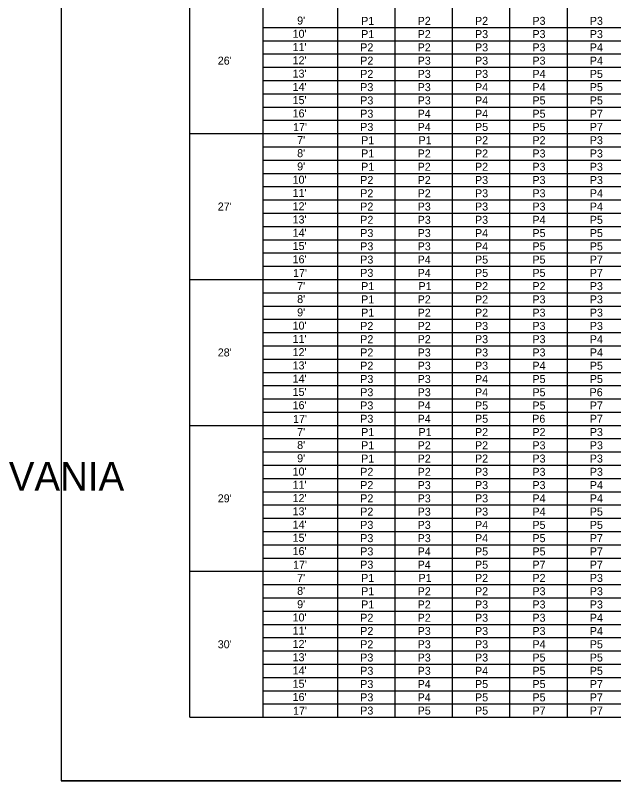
# Model space of a CAD drawing. Extents: x 637580 to 641008, y 294594 to 295782.
# Drawn here: x 640126.1 to 640350.4, y 295202.6 to 295489.6 of the extents above; entities that cross this region are included whole.
import ezdxf

# ---------------------------------------------------------------- set-up
doc = ezdxf.new("R2010")
doc.units = 0
doc.layers.add('1', color=7, linetype='Continuous')
doc.layers.add('2', color=7, linetype='Continuous')

msp = doc.modelspace()

# ---------------------------------------------------------------- linework, layer by layer
at = {"layer": '1'}
for p, q in [((640143.31, 295766.63), (640143.31, 295202.63)), ((640191.43, 295226.43), (640191.43, 295743.08)), ((640218.95, 295226.43), (640218.95, 295735.41)), ((640191.43, 295445.22), (640526.66, 295445.22)), ((640191.43, 295390.52), (640526.66, 295390.52)), ((640191.43, 295335.82), (640526.66, 295335.82)), ((640191.43, 295281.12), (640526.66, 295281.12)), ((640191.43, 295226.43), (640526.66, 295226.43)), ((640929.31, 295202.63), (640143.31, 295202.63)), ((640143.31, 295202.63), (640729.31, 295202.63))]:
    msp.add_line(p, q, dxfattribs=at)
at = {"layer": '2'}
for p, q in [((640246.95, 295226.43), (640246.95, 295735.41)), ((640268.47, 295226.43), (640268.47, 295728.06)), ((640289.99, 295226.43), (640289.99, 295728.06)), ((640311.5, 295226.43), (640311.5, 295728.06)), ((640333.02, 295226.43), (640333.02, 295728.06)), ((640218.95, 295485), (640526.66, 295485)), ((640218.95, 295480.02), (640526.66, 295480.02)), ((640218.95, 295475.05), (640526.66, 295475.05)), ((640218.95, 295470.08), (640526.66, 295470.08)), ((640218.95, 295465.11), (640526.66, 295465.11)), ((640218.95, 295460.13), (640526.66, 295460.13)), ((640218.95, 295455.16), (640526.66, 295455.16)), ((640218.95, 295450.19), (640526.66, 295450.19)), ((640218.95, 295440.24), (640526.66, 295440.24)), ((640218.95, 295435.27), (640526.66, 295435.27)), ((640218.95, 295430.3), (640526.66, 295430.3)), ((640218.95, 295425.33), (640526.66, 295425.33)), ((640218.95, 295420.35), (640526.66, 295420.35)), ((640218.95, 295415.38), (640526.66, 295415.38)), ((640218.95, 295410.41), (640526.66, 295410.41)), ((640218.95, 295405.44), (640526.66, 295405.44)), ((640218.95, 295400.46), (640526.66, 295400.46)), ((640218.95, 295395.49), (640526.66, 295395.49)), ((640218.95, 295385.55), (640526.66, 295385.55)), ((640218.95, 295380.57), (640526.66, 295380.57)), ((640218.95, 295375.6), (640526.66, 295375.6)), ((640218.95, 295370.63), (640526.66, 295370.63)), ((640218.95, 295365.66), (640526.66, 295365.66)), ((640218.95, 295360.68), (640526.66, 295360.68)), ((640218.95, 295355.71), (640526.66, 295355.71)), ((640218.95, 295350.74), (640526.66, 295350.74)), ((640218.95, 295345.77), (640526.66, 295345.77)), ((640218.95, 295340.79), (640526.66, 295340.79)), ((640218.95, 295330.85), (640526.66, 295330.85)), ((640218.95, 295325.88), (640526.66, 295325.88)), ((640218.95, 295320.9), (640526.66, 295320.9)), ((640218.95, 295315.93), (640526.66, 295315.93)), ((640218.95, 295310.96), (640526.66, 295310.96)), ((640218.95, 295305.99), (640526.66, 295305.99)), ((640218.95, 295301.01), (640526.66, 295301.01)), ((640218.95, 295296.04), (640526.66, 295296.04)), ((640218.95, 295291.07), (640526.66, 295291.07)), ((640218.95, 295286.1), (640526.66, 295286.1)), ((640218.95, 295276.15), (640526.66, 295276.15)), ((640218.95, 295271.18), (640526.66, 295271.18)), ((640218.95, 295266.21), (640526.66, 295266.21)), ((640218.95, 295261.23), (640526.66, 295261.23)), ((640218.95, 295256.26), (640526.66, 295256.26)), ((640218.95, 295251.29), (640526.66, 295251.29)), ((640218.95, 295246.32), (640526.66, 295246.32)), ((640218.95, 295241.34), (640526.66, 295241.34)), ((640218.95, 295236.37), (640526.66, 295236.37)), ((640218.95, 295231.4), (640526.66, 295231.4))]:
    msp.add_line(p, q, dxfattribs=at)

# ---------------------------------------------------------------- texts
at = {"layer": '1'}
for s, height, p in [("9'", 3, (640231.71, 295486.09)), ('P1', 3, (640255.7, 295485.98)), ('P2', 3, (640276.88, 295485.98)), ('P2', 3, (640298.39, 295485.98)), ('P3', 3, (640319.91, 295485.98)), ('P3', 3, (640341.42, 295485.98)), ("10'", 3, (640230.01, 295481.12)), ('P1', 3, (640255.7, 295481.01)), ('P2', 3, (640276.88, 295481.01)), ('P3', 3, (640298.39, 295481.01)), ('P3', 3, (640319.91, 295481.01)), ('P3', 3, (640341.42, 295481.01)), ("11'", 3, (640230.01, 295476.15)), ('P2', 3, (640255.36, 295476.04)), ('P2', 3, (640276.88, 295476.04)), ('P3', 3, (640298.39, 295476.04)), ('P3', 3, (640319.91, 295476.04)), ('P4', 3, (640341.42, 295476.04)), ("26'", 3, (640201.95, 295471.06)), ("12'", 3, (640230.01, 295471.18)), ('P2', 3, (640255.36, 295471.06)), ('P3', 3, (640276.88, 295471.06)), ('P3', 3, (640298.39, 295471.06)), ('P3', 3, (640319.91, 295471.06)), ('P4', 3, (640341.42, 295471.06)), ("13'", 3, (640230.01, 295466.2)), ('P2', 3, (640255.36, 295466.09)), ('P3', 3, (640276.88, 295466.09)), ('P3', 3, (640298.39, 295466.09)), ('P4', 3, (640319.91, 295466.09)), ('P5', 3, (640341.42, 295466.09)), ("14'", 3, (640230.01, 295461.23)), ('P3', 3, (640255.36, 295461.12)), ('P3', 3, (640276.88, 295461.12)), ('P4', 3, (640298.39, 295461.12)), ('P4', 3, (640319.91, 295461.12)), ('P5', 3, (640341.42, 295461.12)), ("15'", 3, (640230.01, 295456.26)), ('P3', 3, (640255.36, 295456.15)), ('P3', 3, (640276.88, 295456.15)), ('P4', 3, (640298.39, 295456.15)), ('P5', 3, (640319.91, 295456.15)), ('P5', 3, (640341.42, 295456.15)), ("16'", 3, (640230.01, 295451.29)), ('P3', 3, (640255.36, 295451.17)), ('P4', 3, (640276.88, 295451.17)), ('P4', 3, (640298.39, 295451.17)), ('P5', 3, (640319.91, 295451.17)), ('P7', 3, (640341.42, 295451.17)), ("17'", 3, (640230.17, 295446.14)), ('P3', 3, (640255.36, 295446.2)), ('P4', 3, (640276.88, 295446.2)), ('P5', 3, (640298.39, 295446.2)), ('P5', 3, (640319.91, 295446.2)), ('P7', 3, (640341.42, 295446.2)), ("7'", 3, (640231.71, 295441.25)), ('P1', 3, (640255.7, 295441.23)), ('P1', 3, (640277.22, 295441.23)), ('P2', 3, (640298.39, 295441.23)), ('P2', 3, (640319.91, 295441.23)), ('P3', 3, (640341.42, 295441.23)), ("8'", 3, (640231.71, 295436.37)), ('P1', 3, (640255.7, 295436.26)), ('P2', 3, (640276.88, 295436.26)), ('P2', 3, (640298.39, 295436.26)), ('P3', 3, (640319.91, 295436.26)), ('P3', 3, (640341.42, 295436.26)), ("9'", 3, (640231.71, 295431.4)), ('P1', 3, (640255.7, 295431.28)), ('P2', 3, (640276.88, 295431.28)), ('P2', 3, (640298.39, 295431.28)), ('P3', 3, (640319.91, 295431.28)), ('P3', 3, (640341.42, 295431.28)), ("10'", 3, (640230.01, 295426.42)), ('P2', 3, (640255.36, 295426.31)), ('P2', 3, (640276.88, 295426.31)), ('P3', 3, (640298.39, 295426.31)), ('P3', 3, (640319.91, 295426.31)), ('P3', 3, (640341.42, 295426.31)), ("11'", 3, (640230.01, 295421.45)), ('P2', 3, (640255.36, 295421.34)), ('P2', 3, (640276.88, 295421.34)), ('P3', 3, (640298.39, 295421.34)), ('P3', 3, (640319.91, 295421.34)), ('P4', 3, (640341.42, 295421.34)), ("27'", 3, (640201.95, 295416.37)), ("12'", 3, (640230.01, 295416.48)), ('P2', 3, (640255.36, 295416.37)), ('P3', 3, (640276.88, 295416.37)), ('P3', 3, (640298.39, 295416.37)), ('P3', 3, (640319.91, 295416.37)), ('P4', 3, (640341.42, 295416.37)), ("13'", 3, (640230.01, 295411.51)), ('P2', 3, (640255.36, 295411.39)), ('P3', 3, (640276.88, 295411.39)), ('P3', 3, (640298.39, 295411.39)), ('P4', 3, (640319.91, 295411.39)), ('P5', 3, (640341.42, 295411.39)), ("14'", 3, (640230.01, 295406.53)), ('P3', 3, (640255.36, 295406.42)), ('P3', 3, (640276.88, 295406.42)), ('P4', 3, (640298.39, 295406.42)), ('P5', 3, (640319.91, 295406.42)), ('P5', 3, (640341.42, 295406.42)), ("15'", 3, (640230.01, 295401.56)), ('P3', 3, (640255.36, 295401.45)), ('P3', 3, (640276.88, 295401.45)), ('P4', 3, (640298.39, 295401.45)), ('P5', 3, (640319.91, 295401.45)), ('P5', 3, (640341.42, 295401.45)), ("16'", 3, (640230.01, 295396.59)), ('P3', 3, (640255.36, 295396.48)), ('P4', 3, (640276.88, 295396.48)), ('P5', 3, (640298.39, 295396.48)), ('P5', 3, (640319.91, 295396.48)), ('P7', 3, (640341.42, 295396.48)), ('P3', 3, (640255.36, 295391.5)), ("17'", 3, (640230.17, 295391.44)), ('P4', 3, (640276.88, 295391.5)), ('P5', 3, (640298.39, 295391.5)), ('P5', 3, (640319.91, 295391.5)), ('P7', 3, (640341.42, 295391.5)), ("7'", 3, (640231.71, 295386.55)), ('P1', 3, (640255.7, 295386.53)), ('P1', 3, (640277.22, 295386.53)), ('P2', 3, (640298.39, 295386.53)), ('P2', 3, (640319.91, 295386.53)), ('P3', 3, (640341.42, 295386.53)), ("8'", 3, (640231.71, 295381.67)), ('P1', 3, (640255.7, 295381.56)), ('P2', 3, (640276.88, 295381.56)), ('P2', 3, (640298.39, 295381.56)), ('P3', 3, (640319.91, 295381.56)), ('P3', 3, (640341.42, 295381.56)), ("9'", 3, (640231.71, 295376.7)), ('P1', 3, (640255.7, 295376.59)), ('P2', 3, (640276.88, 295376.59)), ('P2', 3, (640298.39, 295376.59)), ('P3', 3, (640319.91, 295376.59)), ('P3', 3, (640341.42, 295376.59)), ("10'", 3, (640230.01, 295371.73)), ('P2', 3, (640255.36, 295371.61)), ('P2', 3, (640276.88, 295371.61)), ('P3', 3, (640298.39, 295371.61)), ('P3', 3, (640319.91, 295371.61)), ('P3', 3, (640341.42, 295371.61)), ("11'", 3, (640230.01, 295366.75)), ('P2', 3, (640255.36, 295366.64)), ('P2', 3, (640276.88, 295366.64)), ('P3', 3, (640298.39, 295366.64)), ('P3', 3, (640319.91, 295366.64)), ('P4', 3, (640341.42, 295366.64)), ("28'", 3, (640201.95, 295361.67)), ("12'", 3, (640230.01, 295361.78)), ('P2', 3, (640255.36, 295361.67)), ('P3', 3, (640276.88, 295361.67)), ('P3', 3, (640298.39, 295361.67)), ('P3', 3, (640319.91, 295361.67)), ('P4', 3, (640341.42, 295361.67)), ("13'", 3, (640230.01, 295356.81)), ('P2', 3, (640255.36, 295356.7)), ('P3', 3, (640276.88, 295356.7)), ('P3', 3, (640298.39, 295356.7)), ('P4', 3, (640319.91, 295356.7)), ('P5', 3, (640341.42, 295356.7)), ("14'", 3, (640230.01, 295351.84)), ('P3', 3, (640255.36, 295351.72)), ('P3', 3, (640276.88, 295351.72)), ('P4', 3, (640298.39, 295351.72)), ('P5', 3, (640319.91, 295351.72)), ('P5', 3, (640341.42, 295351.72)), ("15'", 3, (640230.01, 295346.86)), ('P3', 3, (640255.36, 295346.75)), ('P3', 3, (640276.88, 295346.75)), ('P4', 3, (640298.39, 295346.75)), ('P5', 3, (640319.91, 295346.75)), ('P6', 3, (640341.34, 295346.75)), ("16'", 3, (640230.01, 295341.89)), ('P3', 3, (640255.36, 295341.78)), ('P4', 3, (640276.88, 295341.78)), ('P5', 3, (640298.39, 295341.78)), ('P5', 3, (640319.91, 295341.78)), ('P7', 3, (640341.42, 295341.78)), ("17'", 3, (640230.17, 295336.74)), ('P3', 3, (640255.36, 295336.81)), ('P4', 3, (640276.88, 295336.81)), ('P5', 3, (640298.39, 295336.81)), ('P6', 3, (640319.83, 295336.81)), ('P7', 3, (640341.42, 295336.81)), ("7'", 3, (640231.71, 295331.85)), ('P1', 3, (640255.7, 295331.83)), ('P1', 3, (640277.22, 295331.83)), ('P2', 3, (640298.39, 295331.83)), ('P2', 3, (640319.91, 295331.83)), ('P3', 3, (640341.42, 295331.83)), ("8'", 3, (640231.71, 295326.97)), ('P1', 3, (640255.7, 295326.86)), ('P2', 3, (640276.88, 295326.86)), ('P2', 3, (640298.39, 295326.86)), ('P3', 3, (640319.91, 295326.86)), ('P3', 3, (640341.42, 295326.86)), ("9'", 3, (640231.71, 295322)), ('P1', 3, (640255.7, 295321.89)), ('P2', 3, (640276.88, 295321.89)), ('P2', 3, (640298.39, 295321.89)), ('P3', 3, (640319.91, 295321.89)), ('P3', 3, (640341.42, 295321.89)), ('COMMONWEALTH OF PENNSYLVANIA', 10.7828, (639900.9, 295311.36)), ("10'", 3, (640230.01, 295317.03)), ('P2', 3, (640255.36, 295316.92)), ('P2', 3, (640276.88, 295316.92)), ('P3', 3, (640298.39, 295316.92)), ('P3', 3, (640319.91, 295316.92)), ('P3', 3, (640341.42, 295316.92)), ("11'", 3, (640230.01, 295312.06)), ('P2', 3, (640255.36, 295311.94)), ('P3', 3, (640276.88, 295311.94)), ('P3', 3, (640298.39, 295311.94)), ('P3', 3, (640319.91, 295311.94)), ('P4', 3, (640341.42, 295311.94)), ("29'", 3, (640201.95, 295306.97)), ("12'", 3, (640230.01, 295307.08)), ('P2', 3, (640255.36, 295306.97)), ('P3', 3, (640276.88, 295306.97)), ('P3', 3, (640298.39, 295306.97)), ('P4', 3, (640319.91, 295306.97)), ('P4', 3, (640341.42, 295306.97)), ("13'", 3, (640230.01, 295302.11)), ('P2', 3, (640255.36, 295302)), ('P3', 3, (640276.88, 295302)), ('P3', 3, (640298.39, 295302)), ('P4', 3, (640319.91, 295302)), ('P5', 3, (640341.42, 295302)), ("14'", 3, (640230.01, 295297.14)), ('P3', 3, (640255.36, 295297.03)), ('P3', 3, (640276.88, 295297.03)), ('P4', 3, (640298.39, 295297.03)), ('P5', 3, (640319.91, 295297.03)), ('P5', 3, (640341.42, 295297.03)), ("15'", 3, (640230.01, 295292.17)), ('P3', 3, (640255.36, 295292.05)), ('P3', 3, (640276.88, 295292.05)), ('P4', 3, (640298.39, 295292.05)), ('P5', 3, (640319.91, 295292.05)), ('P7', 3, (640341.42, 295292.05)), ("16'", 3, (640230.01, 295287.19)), ('P3', 3, (640255.36, 295287.08)), ('P4', 3, (640276.88, 295287.08)), ('P5', 3, (640298.39, 295287.08)), ('P5', 3, (640319.91, 295287.08)), ('P7', 3, (640341.42, 295287.08)), ("17'", 3, (640230.17, 295282.05)), ('P3', 3, (640255.36, 295282.11)), ('P4', 3, (640276.88, 295282.11)), ('P5', 3, (640298.39, 295282.11)), ('P7', 3, (640319.91, 295282.11)), ('P7', 3, (640341.42, 295282.11)), ("7'", 3, (640231.71, 295277.16)), ('P1', 3, (640255.7, 295277.14)), ('P1', 3, (640277.22, 295277.14)), ('P2', 3, (640298.39, 295277.14)), ('P2', 3, (640319.91, 295277.14)), ('P3', 3, (640341.42, 295277.14)), ("8'", 3, (640231.71, 295272.28)), ('P1', 3, (640255.7, 295272.16)), ('P2', 3, (640276.88, 295272.16)), ('P2', 3, (640298.39, 295272.16)), ('P3', 3, (640319.91, 295272.16)), ('P3', 3, (640341.42, 295272.16)), ("9'", 3, (640231.71, 295267.3)), ('P1', 3, (640255.7, 295267.19)), ('P2', 3, (640276.88, 295267.19)), ('P3', 3, (640298.39, 295267.19)), ('P3', 3, (640319.91, 295267.19)), ('P3', 3, (640341.42, 295267.19)), ("10'", 3, (640230.01, 295262.33)), ('P2', 3, (640255.36, 295262.22)), ('P2', 3, (640276.88, 295262.22)), ('P3', 3, (640298.39, 295262.22)), ('P3', 3, (640319.91, 295262.22)), ('P4', 3, (640341.42, 295262.22)), ("11'", 3, (640230.01, 295257.36)), ('P2', 3, (640255.36, 295257.25)), ('P3', 3, (640276.88, 295257.25)), ('P3', 3, (640298.39, 295257.25)), ('P3', 3, (640319.91, 295257.25)), ('P4', 3, (640341.42, 295257.25)), ("30'", 3, (640201.95, 295252.27)), ("12'", 3, (640230.01, 295252.39)), ('P2', 3, (640255.36, 295252.27)), ('P3', 3, (640276.88, 295252.27)), ('P3', 3, (640298.39, 295252.27)), ('P4', 3, (640319.91, 295252.27)), ('P5', 3, (640341.42, 295252.27)), ("13'", 3, (640230.01, 295247.41)), ('P3', 3, (640255.36, 295247.3)), ('P3', 3, (640276.88, 295247.3)), ('P3', 3, (640298.39, 295247.3)), ('P5', 3, (640319.91, 295247.3)), ('P5', 3, (640341.42, 295247.3)), ("14'", 3, (640230.01, 295242.44)), ('P3', 3, (640255.36, 295242.33)), ('P3', 3, (640276.88, 295242.33)), ('P4', 3, (640298.39, 295242.33)), ('P5', 3, (640319.91, 295242.33)), ('P5', 3, (640341.42, 295242.33)), ("15'", 3, (640230.01, 295237.47)), ('P3', 3, (640255.36, 295237.36)), ('P4', 3, (640276.88, 295237.36)), ('P5', 3, (640298.39, 295237.36)), ('P5', 3, (640319.91, 295237.36)), ('P7', 3, (640341.42, 295237.36)), ("16'", 3, (640230.01, 295232.5)), ('P3', 3, (640255.36, 295232.38)), ('P4', 3, (640276.88, 295232.38)), ('P5', 3, (640298.39, 295232.38)), ('P5', 3, (640319.91, 295232.38)), ('P7', 3, (640341.42, 295232.38)), ("17'", 3, (640230.17, 295227.35)), ('P3', 3, (640255.36, 295227.41)), ('P5', 3, (640276.88, 295227.41)), ('P5', 3, (640298.39, 295227.41)), ('P7', 3, (640319.91, 295227.41)), ('P7', 3, (640341.42, 295227.41))]:
    msp.add_text(s, height=height, dxfattribs=at).set_placement(p)

doc.saveas('drawing.dxf')
